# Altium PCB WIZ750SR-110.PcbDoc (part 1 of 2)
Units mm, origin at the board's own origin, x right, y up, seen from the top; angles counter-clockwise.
Board outline 63 x 45 mm, 4 copper layers (Top Layer, Internal Plane 1, Internal Plane 2, Bottom Layer); 95 components, 91 nets, 361 pads, 264 vias.
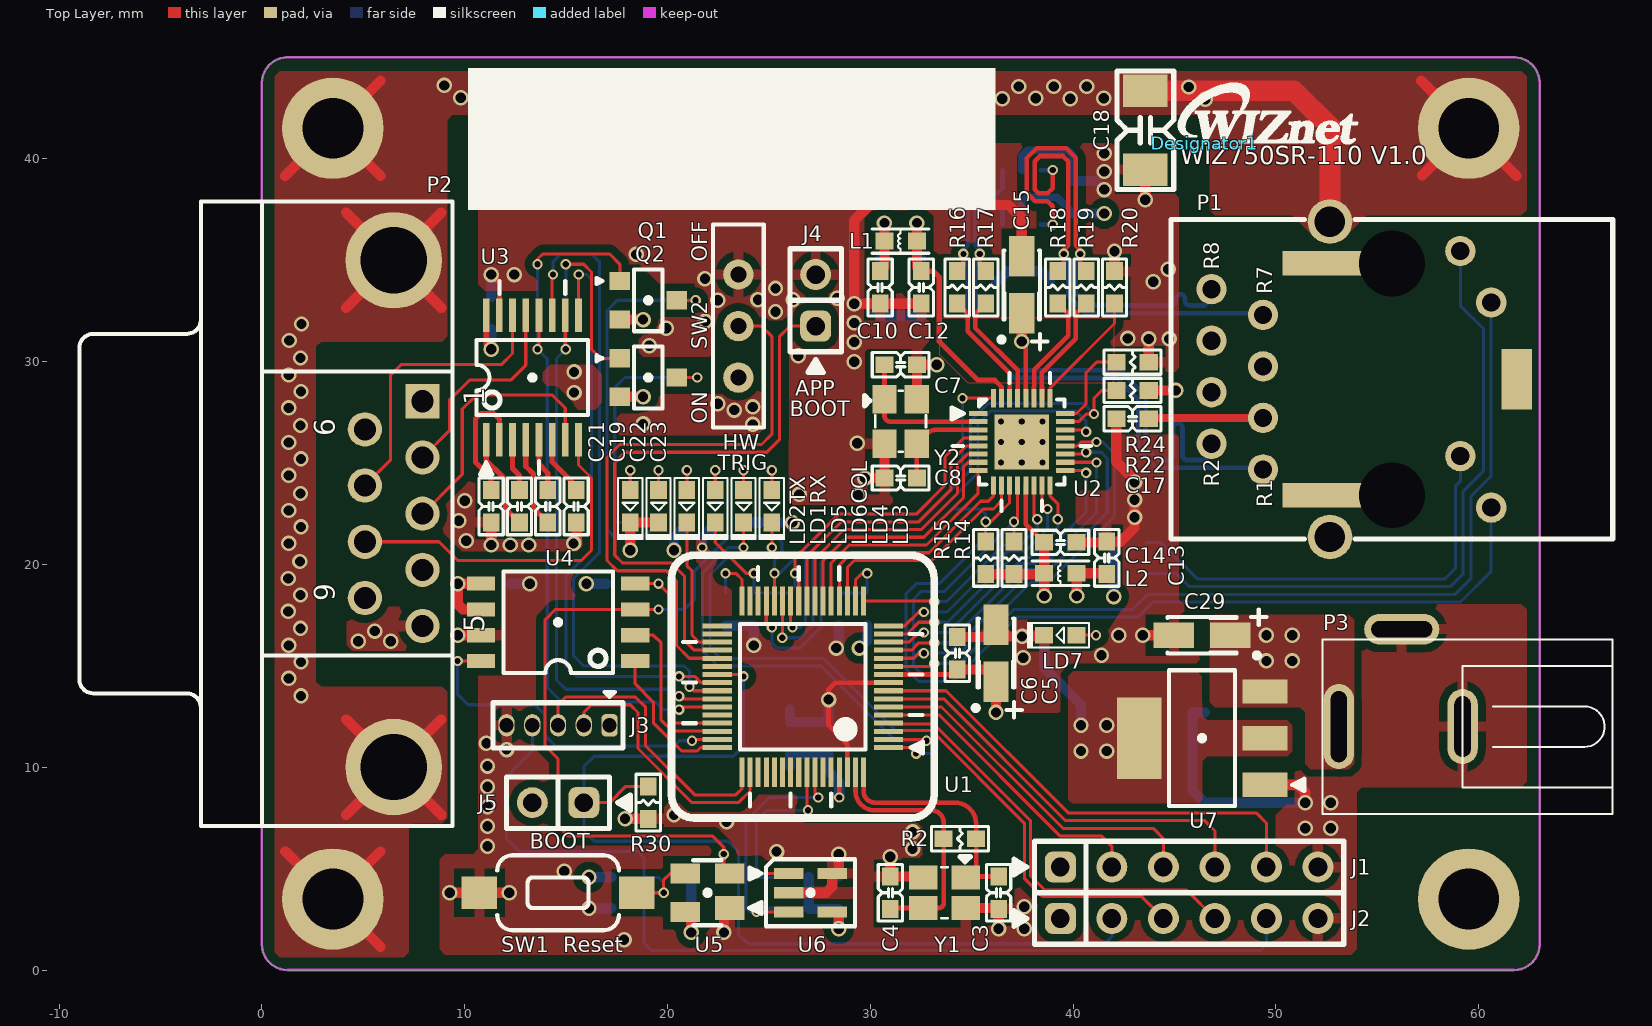
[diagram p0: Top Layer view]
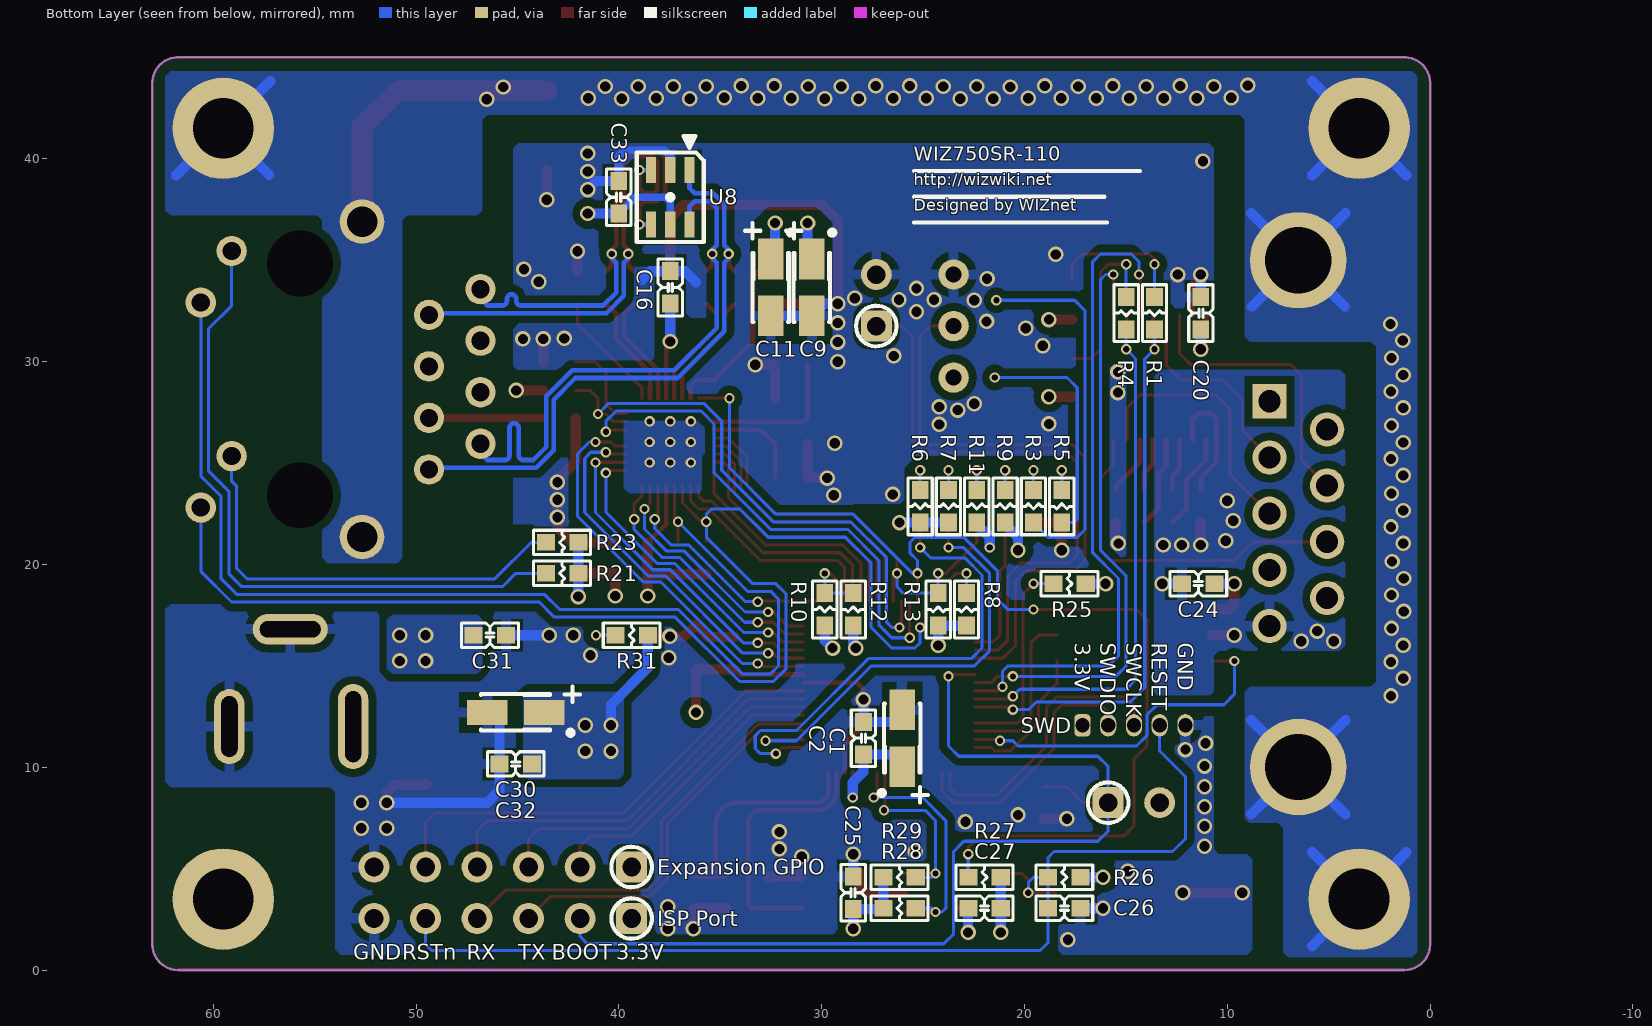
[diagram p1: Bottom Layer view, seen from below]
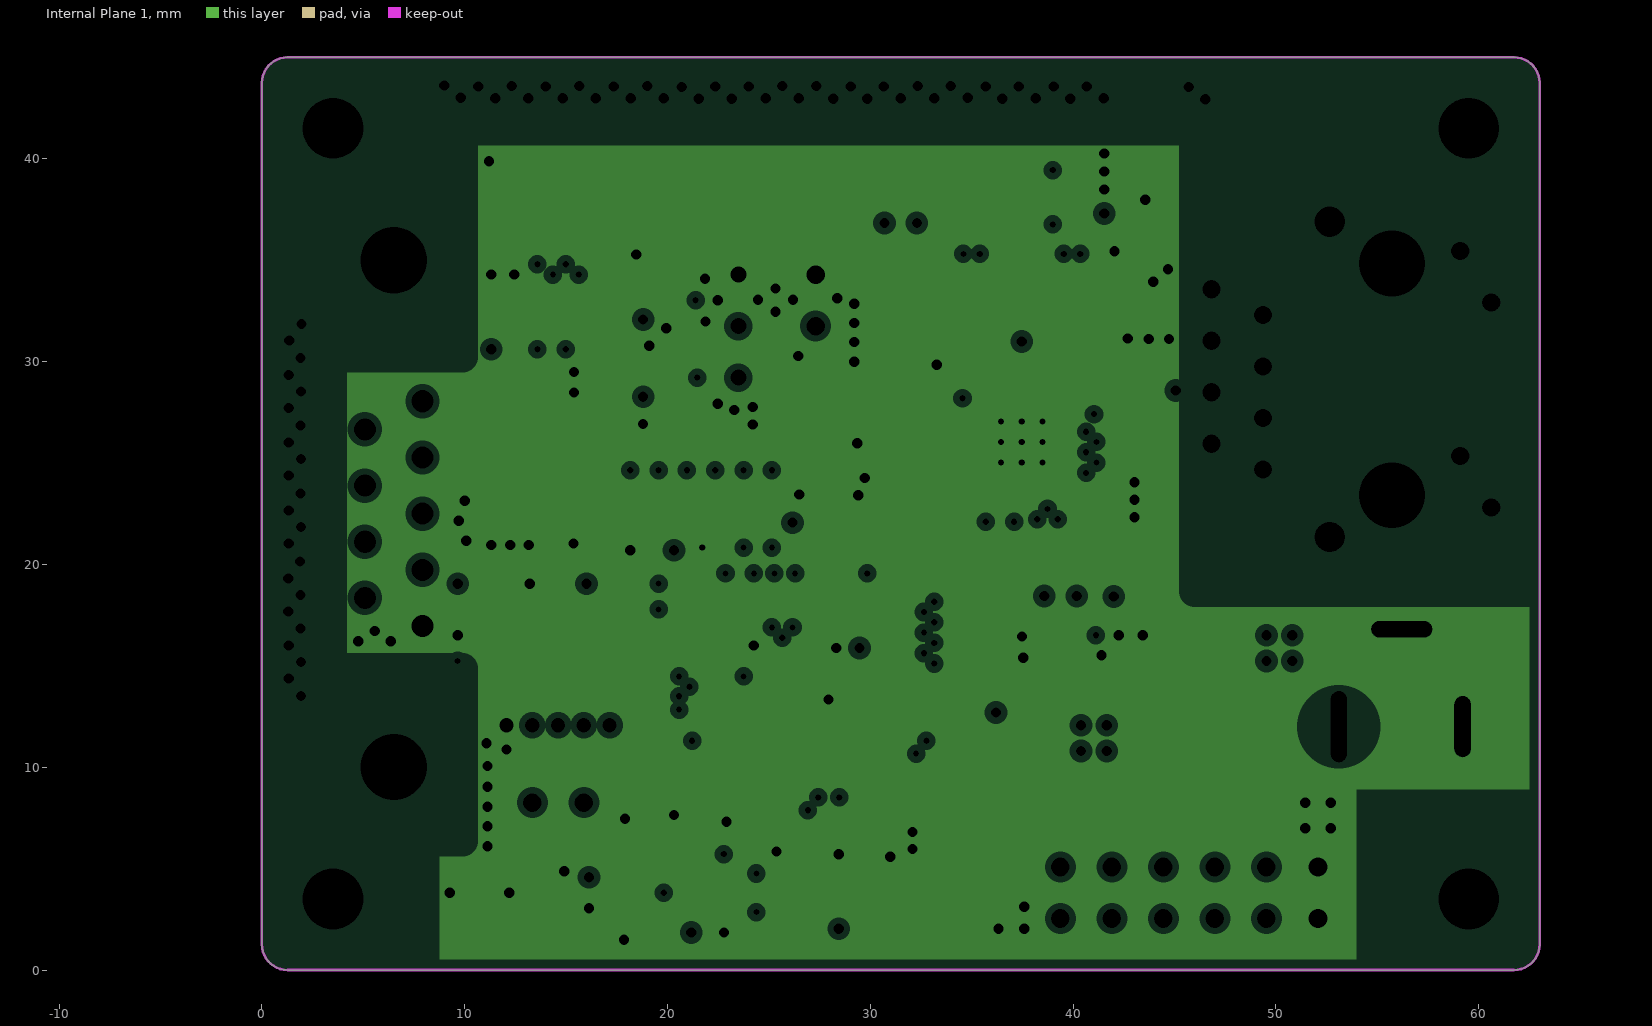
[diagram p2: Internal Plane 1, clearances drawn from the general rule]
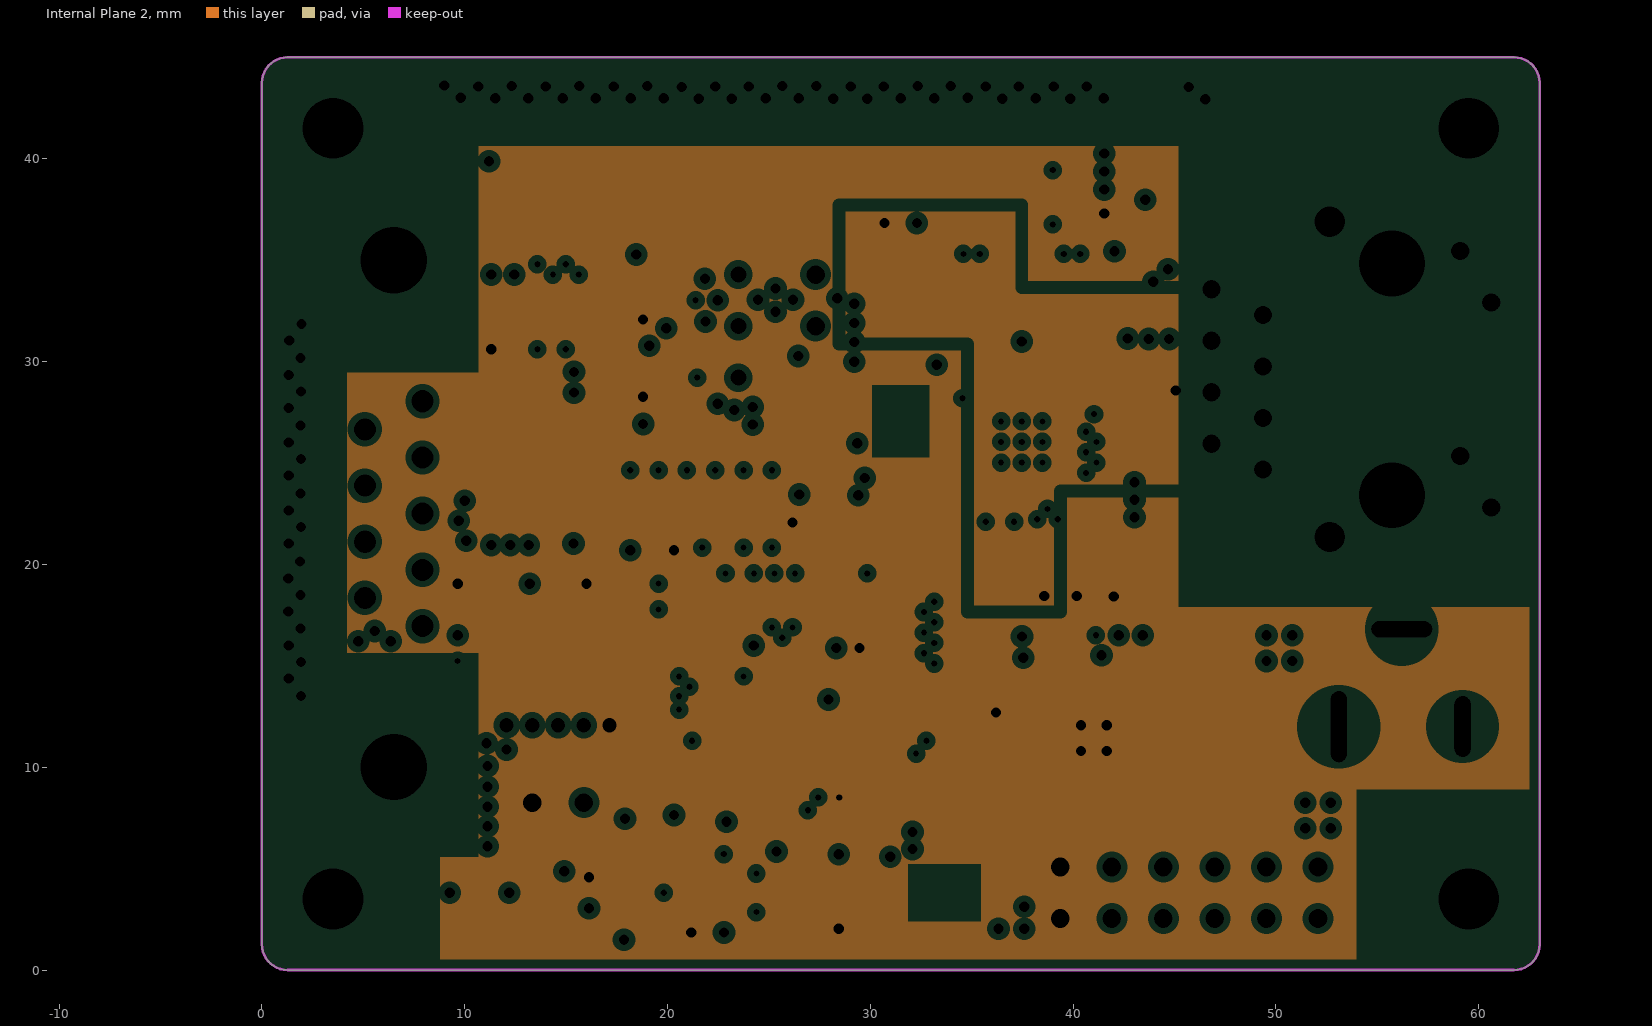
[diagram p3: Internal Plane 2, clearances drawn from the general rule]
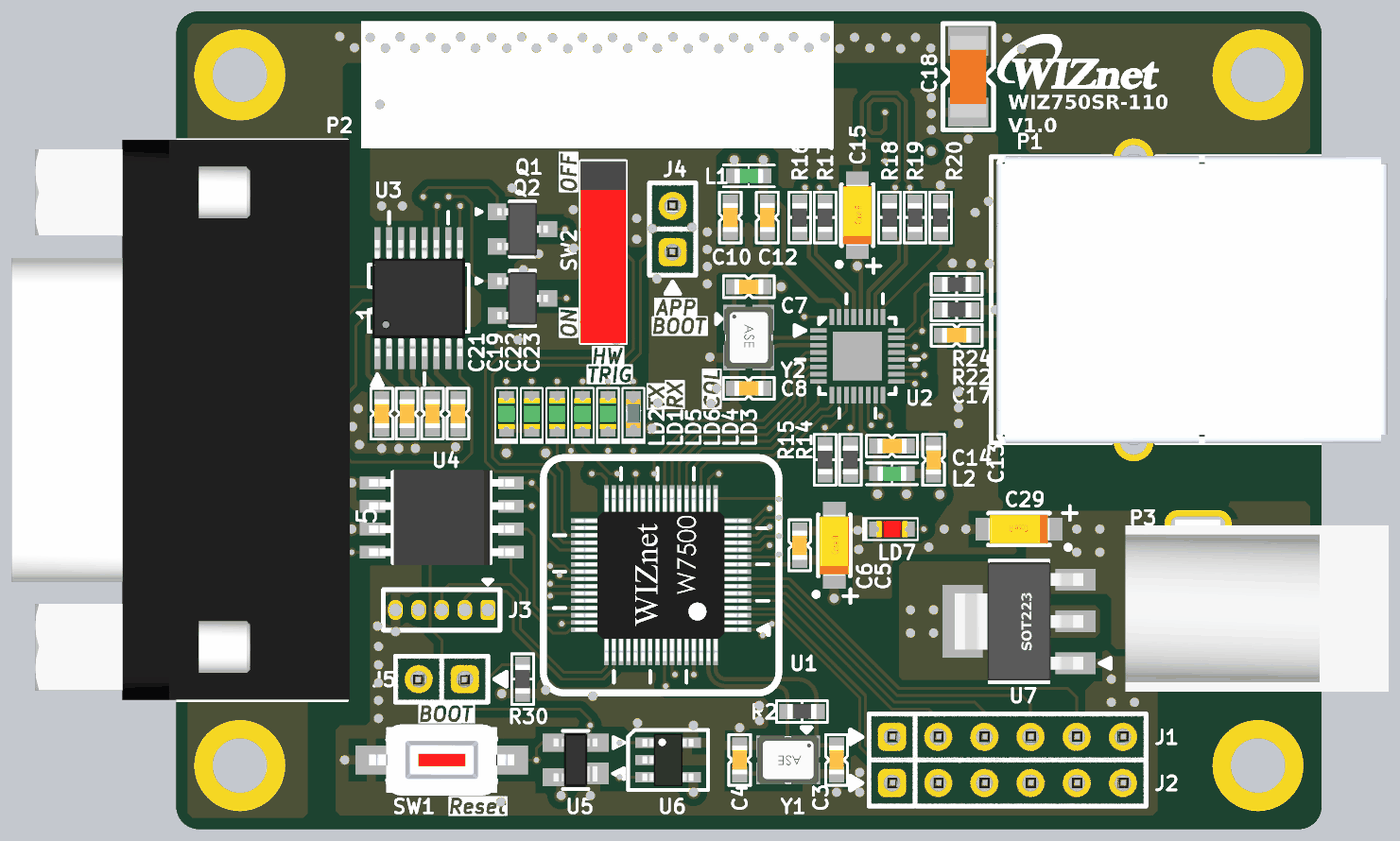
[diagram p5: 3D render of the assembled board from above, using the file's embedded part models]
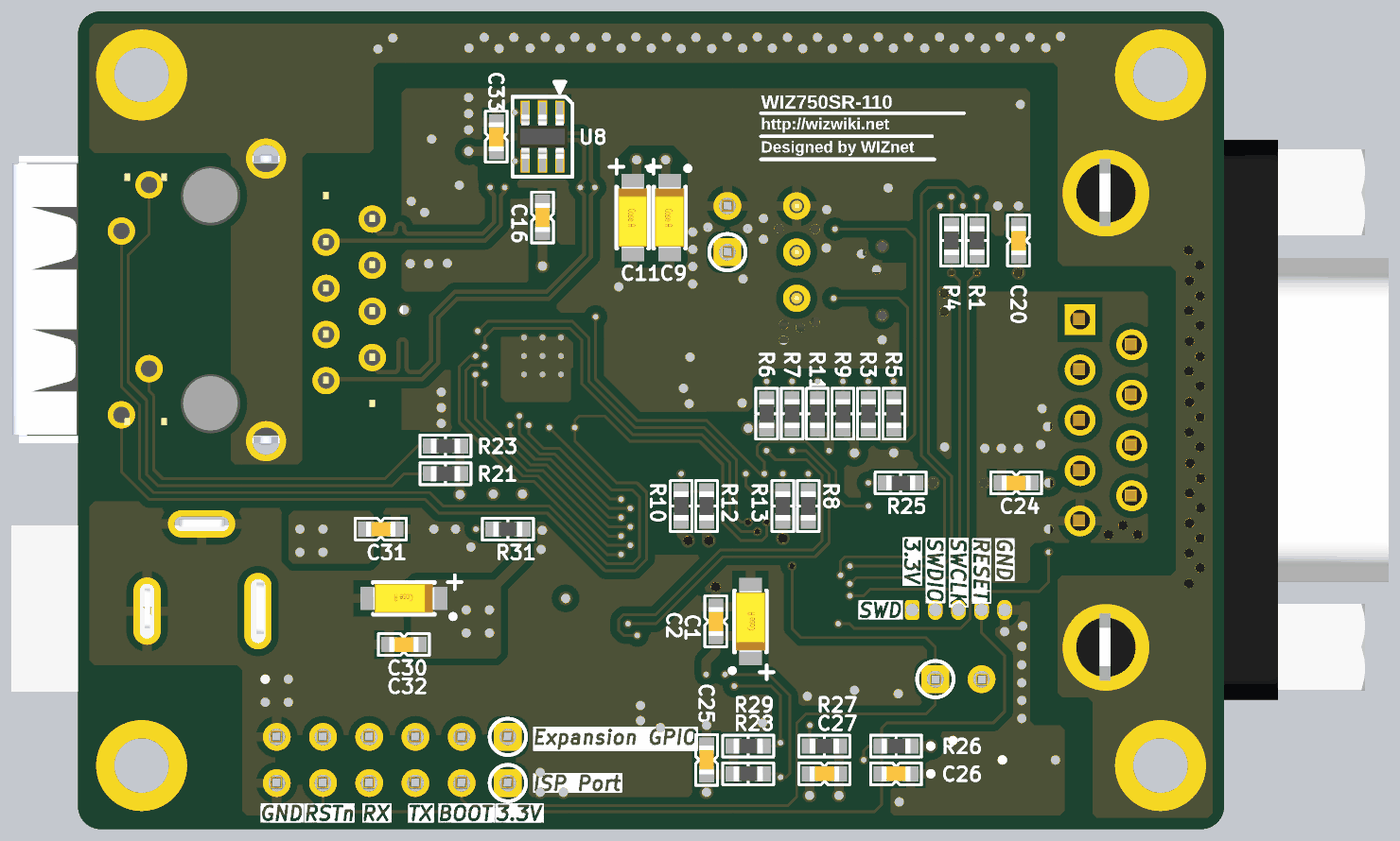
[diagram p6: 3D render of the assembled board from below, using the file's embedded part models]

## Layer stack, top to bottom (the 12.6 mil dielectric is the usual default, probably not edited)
Top Solder: solder mask 0.0102, Solder Resist, Dk 3.5
Top Layer: signal copper 0.0356
Dielectric1: core 0.32, FR-4, Dk 4.8
Internal Plane 1: plane copper 0.0356, net GND
Dielectric5: prepreg 0.32, FR-4, Dk 4.8
Internal Plane 2: plane copper 0.0356, net (Multiple Nets)
Dielectric6: core 0.32, FR-4, Dk 4.8
Bottom Layer: signal copper 0.0356
Bottom Solder: solder mask 0.0102, Solder Resist, Dk 3.5

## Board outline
0,1.27 0,43.73 cw(c1.27,43.73) 1.27,45 61.73,45 cw(c61.73,43.73) 63,43.73 63,1.27 cw(c61.73,1.27) 61.73,0 1.27,0 cw(c1.27,1.27)

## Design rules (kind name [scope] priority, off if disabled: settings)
Clearance [All] p1: gap=0.15 except(0.381: Arc-Poly Track-Poly SMDPad-Poly THPad-Poly Via-Poly Fill-Poly Poly-Poly Poly-Region)
DiffPairsRouting [All] p1: maxlimit=0.152 minlimit=0.152 mostfreqgap=0.152 toplayer_minwidth=0.152 toplayer_maxwidth=0.229 toplayer_prefwidth=0.229 bottomlayer_minwidth=0.152 bottomlayer_maxwidth=0.229 bottomlayer_prefwidth=0.229 maxuncoupledlength=15.24
HoleSize [All] p1: absolutevalues=TRUE maxlimit=4.064 minlimit=0.025 maxpercent=80.000 minpercent=20.000
PlaneClearance [All] p1: clearance=0.305
PlaneConnect [All] p1: planeconnectstyle=Direct reliefexpansion=0.508 reliefentries=4 reliefconductorwidth=0.254 reliefairgap=0.254
PolygonConnect PolygonConnect_2 [IsPad vs IsNamedPolygon('Top Layer-GND') Or  IsNamedPolygon('Bottom Layer-GND')] p1: connectstyle=Relief reliefconductorwidth=0.508 reliefentries=4 polygonreliefangle="90 Angle" airgapwidth=0.381
PolygonConnect PolygonConnect_1 [IsVia] p2: connectstyle=Direct reliefconductorwidth=0.254 reliefentries=4 polygonreliefangle="90 Angle" airgapwidth=0.254
PolygonConnect [All] p3: connectstyle=Direct reliefconductorwidth=0.254 reliefentries=4 polygonreliefangle="90 Angle" airgapwidth=0.254
RoutingVias [All] p1: holewidth=0.305 width=0.508 viastyle="Through Hole" minholewidth=0.305 minwidth=0.508 maxholewidth=0.508 maxwidth=0.762
SolderMaskExpansion [All] p1: expansion=0
Width [All] p1: maxlimit=2.54 minlimit=0.102 preferedwidth=0.152
26 further rules are at their usual default settings.

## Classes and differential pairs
component class 1.WIZ750JR_W7500: LD2
differential pair MDI_T: +MDI_T_P -MDI_T_N
differential pair MDI_R: +MDI_R_P -MDI_R_N
differential pair MDI0_T: +MDI0_T_P -MDI0_T_N
differential pair MDI0_R: +MDI0_R_P -MDI0_R_N
differential pair NewDifferentialPair1: +U_RXD2 -U_TXD2
differential pair NewDifferentialPair2: +U_RXD0 -U_TXD0
differential pair NewDifferentialPair3: +DB_RXD -DB_TXD

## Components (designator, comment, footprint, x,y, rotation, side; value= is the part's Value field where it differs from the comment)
C1 "10uF/16V" "CAP-A Size" 26.035,11.43 r90 bottom
C2 "1uF" CAP-0603 27.94,11.43 r270 bottom
C3 "30pF" CAP-0603 36.322,3.81 r90 top
C4 "30pF" CAP-0603 30.988,3.81 r270 top
C5 "10uF/16V" "CAP-A Size" 36.195,15.621 r90 top
C6 "1uF" CAP-0603 34.29,15.621 r270 top
C7 "27pF" CAP-0603 31.496,29.845 r180 top
C8 "27pF" CAP-0603 31.496,24.257 r0 top
C9 "10uF/16V" "CAP-A Size" 30.48,33.655 r270 bottom
C10 "0.1uF" CAP-0603 30.48,33.655 r90 top
C11 "10uF/16V" "CAP-A Size" 32.512,33.655 r270 bottom
C12 "0.1uF" CAP-0603 32.512,33.655 r90 top
C13 "0.1uF" CAP-0603 41.656,20.32 r270 top
C14 "0.1uF" CAP-0603 39.37,21.082 r0 top
C15 "10uF/16V" "CAP-A Size" 37.465,33.782 r90 top
C16 "0.1uF" CAP-0603 37.465,33.655 r270 bottom
C17 "0.1uF" CAP-0603 42.926,27.178 r0 top
C18 "1nF/2kV" CAP-1808 43.561,41.402 r90 top
C19 "0.1uF" CAP-0603 12.7,22.86 r90 top
C20 "0.1uF" CAP-0603 11.303,32.385 r270 bottom
C21 "0.1uF" CAP-0603 11.303,22.86 r90 top
C22 "0.1uF" CAP-0603 14.097,22.86 r90 top
C23 "0.1uF" CAP-0603 15.494,22.86 r90 top
C24 "0.1uF(NM)" CAP-0603 11.43,19.05 r0 bottom
C25 "0.1uF(NM)" CAP-0603 28.448,3.81 r270 bottom
C26 "0.1uF" CAP-0603 18.034,3.048 r0 bottom
C27 "0.1uF" CAP-0603 21.971,3.048 r180 bottom
C29 "10uF/16V" "CAP-A Size" 46.355,16.51 r180 top
C30 "10uF/16V" "CAP-A Size" 45.085,12.7 r0 bottom
C31 "0.1uF" CAP-0603 46.355,16.51 r0 bottom
C32 "0.1uF" CAP-0603 45.085,10.16 r180 bottom
C33 "0.1uF" CAP-0603 40.005,38.1 r90 bottom
Designator1 "Comment" LOGO-WIZNET(SMALL) 46.482,40.767 r0 top locked
J1 "2.54mm 1x6 Pin Header DIP" IDC-1X6 39.37,5.08 r0 top locked
J2 "2.54mm 1x6 Pin Header DIP(NM)" IDC-1X6 39.37,2.54 r0 top locked
J3 "1.27mm_1x5_Pin_header_DIP(NM)" IDC-1X5(1.27MM) 17.145,12.065 r180 top
J4 "2.54mm 1x2 Pin Header DIP" IDC-1X2 27.305,31.75 r90 top
J5 "2.54mm 1x2 Pin Header DIP" IDC-1X2 15.875,8.255 r180 top
L1 "HH-1M1608-121JT" IND-0603 31.496,35.941 r180 top
L2 "HH-1M1608-121JT" IND-0603 39.37,19.558 r180 top
LD1 "GREEN-0603" LED-0603-GREEN 19.558,22.86 r270 top
LD2 "GREEN-0603" LED-0603-GREEN 18.161,22.86 r270 top
LD3 "BLUE-0603" LED-0603-BLUE 25.146,22.86 r270 top
LD4 "GREEN-0603" LED-0603-GREEN 23.749,22.86 r270 top
LD5 "GREEN-0603" LED-0603-GREEN 20.955,22.86 r270 top
LD6 "GREEN-0603" LED-0603-GREEN 22.352,22.86 r270 top
LD7 "RED-0603" LED-0603-RED 39.37,16.51 r180 top
P1 "BS-RB10005" RJ45-RB10005 63,29.125 r90 top locked
P2 "D-SUB9-MALE" D-SUB9-MALE -3,22.5 r90 top locked
P3 "DC-JACK 2pi" "DC-JACK 2PI" 63,12 r90 top locked
Q1 "Q-MMBT4403" SOT-23-3L 19.05,33.02 r270 top
Q2 "Q-MMBT4403" SOT-23-3L 19.05,29.21 r270 top
R1 "1K" RES-0603 13.589,32.385 r270 bottom
R2 "1M" RES-0603 34.417,6.477 r180 top
R3 "330R" RES-0603 19.558,22.86 r270 bottom
R4 "1K" RES-0603 14.986,32.385 r270 bottom
R5 "330R" RES-0603 18.161,22.86 r90 bottom
R6 "1K" RES-0603 25.146,22.86 r270 bottom
R7 "330R" RES-0603 23.749,22.86 r270 bottom
R8 "4.7K" RES-0603 22.86,17.78 r90 bottom
R9 "330R" RES-0603 20.955,22.86 r270 bottom
R10 "4.7K/NC" RES-0603 29.845,17.78 r270 bottom
R11 "330R" RES-0603 22.352,22.86 r270 bottom
R12 "4.7K" RES-0603 28.448,17.78 r90 bottom
R13 "5.1K" RES-0603 24.257,17.78 r90 bottom
R14 "5.1K" RES-0603 37.084,20.32 r90 top
R15 "5.1K" RES-0603 35.687,20.32 r90 top
R16 "3.3R" RES-0603 34.29,33.655 r270 top
R17 "3.3R" RES-0603 35.687,33.655 r270 top
R18 "3.3R" RES-0603 39.243,33.655 r270 top
R19 "3.3R" RES-0603 40.64,33.655 r270 top
R20 "6.19K / 1%" RES-0603 42.037,33.655 r270 top
R21 "330R" RES-0603 42.799,19.558 r0 bottom
R22 "5.1K" RES-0603 42.926,28.575 r0 top
R23 "330R" RES-0603 42.799,21.082 r0 bottom
R24 "5.1K" RES-0603 42.926,29.972 r180 top
R25 "4.7K(NM)" RES-0603 17.78,19.05 r180 bottom
R26 "4.7K" RES-0603 18.034,4.572 r180 bottom
R27 "4.7K" RES-0603 21.971,4.572 r180 bottom
R28 "4.7K(NM)" RES-0603 26.162,3.048 r0 bottom
R29 "4.7K(NM)" RES-0603 26.162,4.572 r0 bottom
R30 "4.7K" RES-0603 19.05,8.255 r270 top
R31 "330R" RES-0603 39.37,16.51 r0 bottom
SW1 "ITS-1107(SMD)" IT-1107(SMD) 14.605,3.81 r0 top
SW2 "ITS-12H" ITS-12H 23.495,31.75 r270 top
U1 "W7500" W7500-LQFP64 26.67,13.97 r180 top locked
U2 "IP101GR/GRI" QFN32(0.4/4X4) 37.465,26.035 r0 top locked
U3 "SP3232EBEY" TSSOP16(0.65/6.4) 13.335,29.21 r90 top
U4 "AT45DB161E-SHF-T" SO-08-EIAJ 14.605,17.145 r180 top
U5 "MIC811SUY" SOT-143 21.971,3.81 r90 top
U6 "24AA16T-I/OT" SOT-23-5L 27.051,3.81 r0 top
U7 "IL1117C-33ET" SOT-223 46.355,11.43 r90 top locked
U8 "TPD4S009" SOT-23-6L 37.465,38.1 r270 bottom
Y1 "12MHz" OSC-TZ1067B 33.655,3.81 r180 top
Y2 "25MHz" OSC-82J0626 31.496,27.051 r270 top

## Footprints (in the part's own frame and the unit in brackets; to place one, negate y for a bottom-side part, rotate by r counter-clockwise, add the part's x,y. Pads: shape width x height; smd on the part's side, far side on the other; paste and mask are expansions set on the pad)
CAP-0603 [mm] "Ceramic CAP 0603(1608)"
  rect 0.89x0.82 smd: 1(-0.8,0) 2(0.8,0)
  silkscreen extent -1.4,-0.6 1.4,0.6, body extent -0.93,-0.41 0.93,0.41, height 0.81
CAP-1808 [mm] "Ceramic CAP 1808(4520)"
  rect 1.6x2.2 smd: 1(-1.95,0) 2(1.95,0)
  silkscreen extent -2.92,-1.4 2.92,1.4, body extent -2.25,-1.02 2.25,1.01, height 2
"CAP-A Size" [mm] "Tantal CAP A Size EIA/IECQ 3216"
  rect 2x1.25 smd: 1(-1.4,0) 2(1.4,0)
  silkscreen extent -3.17,-1.27 1.7,1.12, body extent -1.7,-0.8 1.7,0.8, height 1.75
D-SUB9-MALE [mm] "D-SUB9, MALE, Right Angle;"
  rect 1.69x1.69 hole 1.09: 1(5.54,-10.92)
  round 1.69 hole 1.09: 2(2.77,-10.92) 3(0,-10.92) 4(-2.77,-10.92) 5(-5.54,-10.92) 6(4.155,-8.08) 7(1.385,-8.08) 8(-1.385,-8.08) 9(-4.155,-8.08)
  round 4.76 hole 3.26: 10(-12.495,-9.5) 11(12.495,-9.5)
  silkscreen extent -15.4,-12.4 15.4,6, body extent -15.38,-12.55 15.43,6.05, height 12.57
"DC-JACK 2PI" [mm] "DC-JACK 2pi"
  oval 4.2x1.5 hole 0.8 slot 3.5 at 0 deg: 1(0,9.9)
  oval 1.5x3.7 hole 0.8 slot 3 at 90 deg: 2(4.8,6.8)
  oval 3.7x1.5 hole 0.8 slot 3 at 0 deg: 3(0,3.8)
  silkscreen extent -4.3,-3.6 4.3,10.7, body extent -4.42,-3.69 5.05,10.79, height 11.18
IDC-1X2 [mil]
  rrect50% 60x60 hole 36: 1(0,0)
  round 60 hole 36: 2(100,0)
  silkscreen extent -90,-50 150,50, body extent -49,-49 151,51, height 336
IDC-1X5(1.27MM) [mm]
  rrect50% 0.8x1.1 hole 0.7: 1(0,0)
  oval 0.8x1.1 hole 0.7: 2(1.27,0) 3(2.54,0) 4(3.81,0) 5(5.08,0)
  silkscreen extent -0.66,-1.65 5.74,1.11
IDC-1X6 [mil] "6-Way 2.54 mm Male Header"
  rrect50% 60x60 hole 36: 1(0,0)
  round 60 hole 36: 2(100,0) 3(200,0) 4(300,0) 5(400,0) 6(500,0)
  silkscreen extent -90,-50 550,50, body extent -49,-49 551,51, height 336
IND-0603 [mm] "Inductor 0603(1608)"
  rect 0.89x0.82 smd: 1(-0.8,0) 2(0.8,0)
  Top Layer pour cut-out: -0.254,0.508 -0.254,-0.508 0.254,-0.508 0.254,0.508
  silkscreen extent -1.4,-0.6 1.4,0.6, body extent -0.8,-0.4 0.8,0.4, height 0.95
IT-1107(SMD) [mm]
  rect 1.75x1.6 smd: 1(-3.875,0) 2(3.875,0)
  silkscreen extent -3,-1.85 3,1.85, body extent -4,-1.8 4,1.8, height 2.6
ITS-12H [mm] "Through Hole Slide Switch SPDT On-On 500mA Slide"
  round 1.5 hole 0.8: 1(0,0) 2(2.54,0) 3(-2.54,0)
  silkscreen extent -5,-1.25 5,1.25, body extent -5,-1.25 5,1.25, height 6.4
LED-0603-BLUE [mm] "LED-0603-GREEN"
  rect 0.89x0.82 smd: 1(-0.8,0) 2(0.8,0)
  silkscreen extent -1.41,-0.65 1.65,0.65, body extent -0.8,-0.4 0.8,0.4, height 0.6
LED-0603-GREEN [mm] "LED-0603-GREEN"
  rect 0.89x0.82 smd: 1(-0.8,0) 2(0.8,0)
  silkscreen extent -1.41,-0.65 1.65,0.65, body extent -0.85,-0.45 0.85,0.45, height 0.9
LED-0603-RED [mm] "LED-0603-RED"
  rect 0.89x0.82 smd: 1(-0.8,0) 2(0.8,0)
  silkscreen extent -1.41,-0.65 1.65,0.65, body extent -0.85,-0.45 0.85,0.45, height 0.9
LOGO-WIZNET(SMALL) [mm]
  silkscreen extent -1.27,0 7.52,2.93
OSC-82J0626 [mm]
  rect 1.4x1.2 smd: 1(-1.1,-0.8) 2(1.1,-0.8) 3(1.1,0.8) 4(-1.1,0.8)
  silkscreen extent -1.5,-1.78 1.5,1.25, body extent -1.7,-1.35 1.7,1.35, height 1.06
OSC-TZ1067B [mm]
  rect 1.4x1.2 smd: 1(-1.05,-0.75) 2(1.05,-0.75) 3(1.05,0.75) 4(-1.05,0.75)
  silkscreen extent -1.27,-1.78 0.15,1.25, body extent -1.7,-1.35 1.7,1.35, height 1.06
QFN32(0.4/4X4) [mm]
  rect 0.9x0.25 smd: 1(-2.15,1.4) 2(-2.15,1) 3(-2.15,0.6) 4(-2.15,0.2) 5(-2.15,-0.2) 6(-2.15,-0.6) 7(-2.15,-1) 8(-2.15,-1.4) 17(2.15,-1.4) 18(2.15,-1) 19(2.15,-0.6) 20(2.15,-0.2) 21(2.15,0.2) 22(2.15,0.6) 23(2.15,1) 24(2.15,1.4)
  rect 0.25x0.9 smd: 9(-1.4,-2.15) 10(-1,-2.15) 11(-0.6,-2.15) 12(-0.2,-2.15) 13(0.2,-2.15) 14(0.6,-2.15) 15(1,-2.15) 16(1.4,-2.15) 25(1.4,2.15) 26(1,2.15) 27(0.6,2.15) 28(0.2,2.15) 29(-0.2,2.15) 30(-0.6,2.15) 31(-1,2.15) 32(-1.4,2.15)
  rect 2.7x2.7 smd: 33(0,0)
  silkscreen extent -3.45,-3.4 3.4,3.4, body extent -2.1,-2.1 2.1,2.1, height 0.76
RES-0603 [mm] "RES-0603"
  rect 0.89x0.82 smd: 1(-0.8,0) 2(0.8,0)
  silkscreen extent -1.4,-0.6 1.4,0.6, body extent -0.82,-0.41 0.83,0.41, height 0.46
RJ45-RB10005 [mm]
  round 2.2 hole 1.5: 0(-7.775,10.34) 0(7.775,10.34)
  round 1.5 hole 0.9: L1(6.325,3.91) L2(3.785,2.39) L3(-3.785,3.91) L4(-6.325,2.39) R1(-4.445,13.64) R2(-3.175,16.18) R3(-1.905,13.64) R4(-0.635,16.18) R5(0.635,13.64) R6(1.905,16.18) R7(3.175,13.64) R8(4.445,16.18)
  round 3 hole 3.25 unplated paste+0 mask+0.102: ""(-5.715,7.29) ""(5.715,7.29)
  rect 1.2x4.7 smd: ""(-5.715,10.34) ""(5.715,10.34)
  rect 3x1.5 smd: ""(0,1.14)
  silkscreen extent -7.88,-3.6 7.88,18.18, body extent -7.97,-3.61 8.03,17.89, height 12.67
SO-08-EIAJ [mm]
  rect 1.4x0.7 smd: 1(-3.8,1.905) 2(-3.8,0.635) 3(-3.8,-0.635) 4(-3.8,-1.905) 5(3.8,-1.905) 6(3.8,-0.635) 7(3.8,0.635) 8(3.8,1.905)
  silkscreen extent -2.7,-2.5 2.7,2.5, body extent -4,-2.62 4,2.63, height 2.58
SOT-23-3L [mm]
  rect 0.9x1 smd: 1(-0.95,-1.4) 2(0.95,-1.4) 3(0,1.4)
  silkscreen extent -1.53,-2.55 1.53,0.7, body extent -1.45,-1.4 1.45,1.4, height 1.28
SOT-23-5L [mm]
  rect 1.45x0.55 smd: 1(-1.075,0.95) 2(-1.075,0) 3(-1.075,-0.95) 4(1.075,-0.95) 5(1.075,0.95)
  silkscreen extent -3.01,-1.65 2.2,1.65, body extent -1.4,-1.45 1.4,1.45, height 1.45
SOT-23-6L [mm]
  rect 1.27x0.508 smd paste-0.07: 1(-1.34,0.95) 2(-1.34,0) 3(-1.34,-0.95) 4(1.34,-0.95) 5(1.34,0) 6(1.34,0.95)
  silkscreen extent -3.02,-1.65 2.2,1.65, body extent -1.21,-1.4 1.21,1.4, height 1.09
SOT-143 [mm]
  rect 1.2x1.44 smd: 1(-0.75,-1.1)
  rect 1x1.44 smd: 2(0.95,-1.1) 3(0.95,1.1) 4(-0.95,1.1)
  silkscreen extent -1.6,-2.65 1.6,0.7, body extent -1.46,-1.21 1.46,1.21, height 1
SOT-223 [mm]
  rect 1.2x2.2 smd: 1(-2.3,-3.1) 2(0,-3.1) 3(2.3,-3.1)
  rect 4x2.2 smd: 4(0,3.1)
  silkscreen extent -3.35,-5.03 3.35,1.63, body extent -3.25,-3.53 3.25,3.52, height 1.82
TSSOP16(0.65/6.4) [mil]
  rect 65x13 smd: 1(-121.04,89.57) 2(-121.04,63.98) 3(-121.04,38.39) 4(-121.04,12.8) 5(-121.04,-12.8) 6(-121.04,-38.39) 7(-121.04,-63.98) 8(-121.04,-89.57) 9(121.04,-89.57) 10(121.04,-63.98) 11(121.04,-38.39) 12(121.04,-12.8) 13(121.04,12.8) 14(121.04,38.39) 15(121.04,63.98) 16(121.04,89.57)
  silkscreen extent -188,-108 187,108, body extent -126,-100 126,100, height 47
W7500-LQFP64 [mm] "WIZnet ARM Cortex-M0, LQFP64, Pitch 0.40mm"
  rect 1.45x0.25 smd: 1(-4.225,3) 2(-4.225,2.6) 3(-4.225,2.2) 4(-4.225,1.8) 5(-4.225,1.4) 6(-4.225,1) 7(-4.225,0.6) 8(-4.225,0.2) 9(-4.225,-0.2) 10(-4.225,-0.6) 11(-4.225,-1) 12(-4.225,-1.4) 13(-4.225,-1.8) 14(-4.225,-2.2) 15(-4.225,-2.6) 16(-4.225,-3) 33(4.225,-3) 34(4.225,-2.6) 35(4.225,-2.2) 36(4.225,-1.8) 37(4.225,-1.4) 38(4.225,-1) 39(4.225,-0.6) 40(4.225,-0.2) 41(4.225,0.2) 42(4.225,0.6) 43(4.225,1) 44(4.225,1.4) 45(4.225,1.8) 46(4.225,2.2) 47(4.225,2.6) 48(4.225,3)
  rect 0.25x1.45 smd: 17(-3,-4.225) 18(-2.6,-4.225) 19(-2.2,-4.225) 20(-1.8,-4.225) 21(-1.4,-4.225) 22(-1,-4.225) 23(-0.6,-4.225) 24(-0.2,-4.225) 25(0.2,-4.225) 26(0.6,-4.225) 27(1,-4.225) 28(1.4,-4.225) 29(1.8,-4.225) 30(2.2,-4.225) 31(2.6,-4.225) 32(3,-4.225) 49(3,4.225) 50(2.6,4.225) 51(2.2,4.225) 52(1.8,4.225) 53(1.4,4.225) 54(1,4.225) 55(0.6,4.225) 56(0.2,4.225) 57(-0.2,4.225) 58(-0.6,4.225) 59(-1,4.225) 60(-1.4,4.225) 61(-1.8,4.225) 62(-2.2,4.225) 63(-2.6,4.225) 64(-3,4.225)
  silkscreen extent -6.48,-6.48 6.48,6.48, body extent -4.73,-4.74 4.73,4.72, height 1

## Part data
C1 C5 C9 C11 C15 C29 C30: library part "CAP-A Size", "Tantla CAP A Size EIA/IECQ 3216"
C2 C3 C4 C6 C7 C8 C10 C12 C13 C14 C16 C17 C19 C20 C21 C22 C23 C24 C25 C26 C27: library part CAP-0402, "Ceramic CAP 0402(1005)"
C18: library part CAP-1808, "Ceramic CAP 1808(4520)"
C31 C32 C33: library part CAP-0603, "Ceramic CAP 0603(1608)"
J2: library part "Header 6", "Header, 6-Pin"
J3: library part 1.27mm_1x5_Pin_header_DIP, "1.27mm_1x5_Pin_header_DIP"
J4 J5: library part "Header 1x2", "pin header 2.54mm 1x2"
L1 L2: library part IND-0603, "Inductor 0603(1608)"
LD1 LD2 LD3 LD4 LD5 LD6 LD7: library part LED-0603, "LED-0603"
P1: library part RB1-125BAG1A, "10/100 BASE-TX MAGJACK"
P2: "D-SUB-9, MALE,  Right Angle"
Q1 Q2: "PNP General-Purpose Amplifier"
R1 R2 R3 R4 R5 R6 R7 R8 R9 R10 R12 R13 R16 R17 R18 R19 R20 R21 R22 R23 R24 R25 R26 R27 R28 R29 R30: library part RES-0402, "RES-0402"
R11 R31: library part RES-0603, "RES-0603"
R14 R15: library part RES-0603, "RES-0402"
SW1: "TACT SW, SMD"
SW2: "Slide Switch"
U1: "WIZnet ARM Cortex-M0"
U3: "True +3.0V to +5.5V RS-232 Transceivers TSSOP16"
U4: "16-Mbit DataFlash, 2.3V or 2.5V Minimum SPI Serial Flash Memory"
U5: "Microprocessor Reset Circuits"
U6: library part 24AAxxT-i-OT, "SOT-23"
U7: "1A, 3.3V"
U8: library part tpd4s009, "6-PIN SOT DBVor DCK Package"
Y1: library part OSC-TZ1067B-12MHz, "X-tal 12MHz,3.2x2.5 SMD, CL=20pF"
Y2: library part OSC-82J0626-25MHz, "X-tal 25MHz,3.2x2.5 SMD, CL=18pF"

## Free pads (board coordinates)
  round 5 hole 3: 0(3.5,3.5) 0(3.5,41.5) 0(59.5,3.5) 0(59.5,41.5)

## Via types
v1: diameter 0.762, hole 0.508, Top Layer to Bottom Layer, tented both sides, 186 vias
v2: diameter 0.508, hole 0.305, Top Layer to Bottom Layer, tented both sides, 78 vias

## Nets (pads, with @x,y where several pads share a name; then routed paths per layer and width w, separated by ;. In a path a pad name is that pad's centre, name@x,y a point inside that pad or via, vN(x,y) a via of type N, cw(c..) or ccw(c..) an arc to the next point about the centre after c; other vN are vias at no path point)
5V: C29.1 C31.2 P3.1 U7.3
  other v1: 49.53,15.24 50.8,15.24 49.53,16.51 50.8,16.51
APP_BOOT: J4.1 U1.36 | length 29.1
  Top Layer w0.152: U1.36@22.445,15.77 21.314,15.77 20.828,16.256 20.828,19.431 20.193,20.066 17.78,20.066 17.399,20.447 17.399,25.019 17.907,25.527 24.892,25.527 25.527,26.162 25.527,31.242 26.035,31.75 J4.1@27.305,31.75
BOOT: J2.2 J5.1 R30.1 U1.39 | length 51.5
  Top Layer w0.152: J5.1@15.875,8.255 17.145,8.255 17.945,9.055 R30.1@19.05,9.055 ; U1.39@22.445,14.57 23.657,14.57 v2(23.749,14.478)
  Bottom Layer w0.152: v2(23.749,14.478) 23.749,11.049 23.241,10.541 16.383,10.541 15.875,10.033 J5.1@15.875,8.255 15.875,6.858 16.383,6.35 22.987,6.35 23.495,5.842 23.495,1.778 23.978,1.295 41.554,1.295 41.91,1.651 J2.2@41.91,2.54
CH_GND: C18.2 P1.0 P2.10 P2.11 pad.0@3.5,3.5 pad.0@3.5,41.5 pad.0@59.5,41.5 | length 126.6
  Top Layer w0.508: 1.151,5.849 pad.0@3.5,3.5 ; 1.151,39.151 pad.0@3.5,41.5 ; 4.151,7.656 P2.10@6.5,10.005 ; 4.151,12.354 P2.10@6.5,10.005 ; 4.151,32.646 P2.11@6.5,34.995 ; 4.151,37.344 P2.11@6.5,34.995 ; 5.849,1.151 pad.0@3.5,3.5 ; 5.849,5.849 pad.0@3.5,3.5 ; 5.849,39.151 pad.0@3.5,41.5 ; 5.849,43.849 pad.0@3.5,41.5 ; 8.849,7.656 P2.10@6.5,10.005 ; 8.849,12.354 P2.10@6.5,10.005 ; 8.849,32.646 P2.11@6.5,34.995 ; 8.849,37.344 P2.11@6.5,34.995 ; 57.151,43.849 pad.0@59.5,41.5 pad.0@59.517,41.483 ; 57.214,39.18 pad.0@59.517,41.483 ; pad.0@59.563,41.529 pad.0@59.517,41.483 ; 61.849,39.151 pad.0@59.517,41.483
  Top Layer w1.016: C18.2@43.561,43.352 50.882,43.352 52.66,41.574 P1.0@52.66,36.9
  Bottom Layer w0.508: 1.185,5.815 pad.0@3.5,3.5 ; 1.185,39.185 pad.0@3.5,41.5 ; 4.185,7.69 P2.10@6.5,10.005 ; 4.185,12.32 P2.10@6.5,10.005 ; 4.185,37.31 P2.11@6.46,35.035 ; 4.219,32.714 P2.11@6.5,34.995 ; 5.815,1.185 pad.0@3.5,3.5 ; 5.815,5.815 pad.0@3.5,3.5 ; 5.815,39.185 pad.0@3.5,41.5 ; 5.815,43.815 pad.0@3.5,41.5 ; 8.781,32.714 P2.11@6.5,34.995 ; 8.815,7.69 P2.10@6.5,10.005 ; 8.815,12.32 P2.10@6.5,10.005 ; 8.815,37.31 P2.11@6.517,35.012 ; 57.185,43.815 pad.0@59.5,41.5 pad.0@59.517,41.483 ; 57.248,39.214 pad.0@59.517,41.483 ; pad.0@59.563,41.529 pad.0@59.517,41.483 ; 61.815,39.185 pad.0@59.517,41.483 ; P2.11@6.46,35.035 6.477,35.052 P2.11@6.517,35.012 ; P2.11@6.46,35.035 P2.11@6.5,34.995 ; P2.11@6.5,34.995 P2.11@6.517,35.012
  other v1: 1.93,13.513 1.321,14.376 1.93,15.189 1.321,16.002 1.905,16.84 1.295,17.678 1.905,18.491 1.295,19.304 1.88,20.142 1.321,21.031 1.93,21.844 1.321,22.657 1.905,23.495 1.321,24.384 1.93,25.197 1.321,26.01 1.905,26.848 1.321,27.711 1.93,28.524 1.321,29.337 1.905,30.175 1.346,31.039 1.956,31.852 46.507,42.926 21.539,42.951 23.165,42.951 28.169,42.951 29.845,42.951 36.5,42.951 39.853,42.951 11.506,42.977 13.132,42.977 14.834,42.977 16.459,42.977 18.186,42.977 19.812,42.977 24.841,42.977 26.467,42.977 31.496,42.977 33.147,42.977 38.151,42.977 41.504,42.977 9.804,43.002 34.798,43.002 20.701,43.536 45.695,43.536 10.668,43.561 13.995,43.561 17.348,43.561 22.352,43.561 24.003,43.561 29.032,43.561 30.658,43.561 35.687,43.561 37.313,43.561 39.04,43.561 40.665,43.561 12.319,43.586 15.646,43.586 18.999,43.586 25.654,43.586 27.33,43.586 32.334,43.586 33.96,43.586 8.992,43.612
DB_CTS: P2.8 U3.8 | length 17.5
  Top Layer w0.152: P2.8@5.08,21.115 8.73,21.115 9.652,20.193 15.748,20.193 16.256,20.701 16.256,24.257 15.61,24.903 U3.8@15.61,26.136
DB_RTS: P2.7 U3.14 | length 14.3
  Top Layer w0.152: P2.7@5.08,23.885 6.35,25.155 6.35,29.337 6.858,29.845 11.811,29.845 12.36,30.394 U3.14@12.36,32.284
DB_RXD: P2.2 U3.13 | length 10.3
  Top Layer w0.152: P2.2@7.92,25.27 9.246,26.596 9.246,28.092 10.236,29.083 12.268,29.083 13.01,29.825 U3.13@13.01,32.284
DB_TXD: P2.3 U3.7 | length 13.2
  Top Layer w0.152: P2.3@7.92,22.5 7.945,22.5 9.614,24.168 9.881,24.436 9.881,27.661 10.566,28.346 14.326,28.346 14.96,27.712 U3.7@14.96,26.136
DUP: R10.1 R12.2 U1.18 | length 4.1
  Top Layer w0.152: U1.18@29.27,18.195 29.27,19.237 29.591,19.558 v2(29.845,19.558)
  Bottom Layer w0.152: R12.2@28.448,18.58 R10.1@29.845,18.58 v2(29.845,19.558)
EX_RESETN: C26.2 J2.5 J3.4 R26.1 SW1.2 U5.3 | length 54.5
  Top Layer w0.152: SW1.2@18.48,3.81 v2(19.812,3.81) 19.812,4.445 20.127,4.76 U5.3@20.871,4.76
  Bottom Layer w0.152: J3.4@13.335,12.065 13.335,10.795 12.065,9.525 12.065,6.477 12.7,5.842 18.542,5.842 18.834,5.55 R26.1@18.834,4.572 ; v2(19.812,3.81) 19.812,4.318 19.558,4.572 R26.1@18.834,4.572 ; J2.5@49.53,2.54 49.53,1.27 49.225,0.965 19.228,0.965 18.834,1.359 C26.2@18.834,3.048 R26.1@18.834,4.572
EXPANSION_GPIO_A: J1.5 U1.8 | length 23.5
  Top Layer w0.152: U1.8@30.895,13.77 33.728,13.77 39.751,7.747 49.022,7.747 49.53,7.239 J1.5@49.53,5.08
EXPANSION_GPIO_B: J1.4 U1.7 | length 20.6
  Top Layer w0.152: U1.7@30.895,13.37 33.62,13.37 39.624,7.366 46.482,7.366 46.99,6.858 J1.4@46.99,5.08
EXPANSION_GPIO_C: J1.3 U1.6 | length 17.6
  Top Layer w0.152: U1.6@30.895,12.97 33.512,12.97 39.497,6.985 43.942,6.985 44.45,6.477 J1.3@44.45,5.08
EXPANSION_GPIO_D: J1.2 U1.5 | length 14.7
  Top Layer w0.152: U1.5@30.895,12.57 33.404,12.57 39.37,6.604 41.402,6.604 41.91,6.096 J1.2@41.91,5.08
GND: C1.2 C2.1 C3.1 C4.1 C5.2 C6.1 C7.1 C8.1 C9.2 C10.1 C11.2 C12.1 C13.1 C14.2 C15.2 C16.1 C17.1 C18.1 C20.1 C21.1 C23.1 C24.2 C25.1 C26.1 C27.1 C29.2 C30.2 C31.1 C32.1 C33.2 J1.6 J2.6 J3.5 J4.2 LD1.2 LD2.2 LD7.2 P2.5 P3.2 P3.3 R8.1 R11.2 R12.1 R13.1 R20.1 R24.1 R30.2 SW1.1 SW2.3 U1.9 U1.62 U2.33 U3.15 U4.7 U5.1 U6.2 U6.5 U7.1 U8.2 Y1.2 Y1.4 Y2.2 Y2.4 | length 114.4
  Top Layer w0.229: U1.62@28.87,9.745 28.87,11.135 27.94,12.065 v1(27.94,13.335) 27.94,13.843 28.267,14.17 U1.9@30.895,14.17
  Top Layer w0.254: v1(11.303,34.29) 11.71,33.883 U3.15@11.71,32.284
  Top Layer w0.508: v1(9.271,3.81) SW1.1@10.73,3.81 v1(12.192,3.81) ; v1(9.652,16.51) U4.7@10.805,16.51 ; v1(11.303,20.955) C21.1@11.303,22.06 ; v1(15.367,21.031) 15.519,21.184 15.519,22.035 C23.1@15.494,22.06 ; v1(17.907,7.455) R30.2@19.05,7.455 ; v1(18.161,20.701) LD2.2@18.161,22.06 LD1.2@19.558,22.06 ; v1(22.784,1.854) 22.784,2.646 22.835,2.696 22.771,2.76 U5.1@23.071,3.06 ; U6.2@25.976,3.81 27.813,3.81 28.126,4.123 U6.5@28.126,4.76 28.448,4.76 v1(28.448,5.715) ; v1(29.718,24.257) C8.1@30.696,24.257 Y2.2@30.696,25.951 ; v1(30.988,5.588) C4.1@30.988,4.61 32.555,4.61 Y1.2@32.605,4.56 ; Y2.4@32.296,28.151 C7.1@32.296,29.845 v1(33.274,29.845) ; C12.1@32.512,32.855 C10.1@30.48,32.855 v1(29.21,32.855) 29.21,36.957 29.972,37.719 36.83,37.719 37.465,37.084 C15.2@37.465,35.182 ; C6.1@34.29,16.421 35.595,16.421 C5.2@36.195,17.021 36.768,16.448 v1(37.481,16.448) 38.508,16.448 LD7.2@38.57,16.51 ; Y1.4@34.705,3.06 36.272,3.06 C3.1@36.322,3.01 v1(36.322,2.032) ; C14.2@40.17,21.082 41.618,21.082 C13.1@41.656,21.12 42.329,21.12 43.028,21.819 v1(43.028,23.19) ; R20.1@42.037,34.455 v1(42.037,35.433) ; C17.1@42.126,27.178 42.126,25.057 43.028,24.155 v1(43.028,24.054) ; v1(43.434,16.51) C29.2@44.955,16.51 ; v1(43.561,37.973) C18.1@43.561,39.452 ; R24.1@43.726,29.972 v1(43.726,31.115) ; U7.1@49.455,9.13 51.068,9.13 51.435,8.763 v1(51.435,8.255)
  Bottom Layer w0.381: U8.2@37.465,39.44 37.465,40.132 37.748,40.415 39.722,40.415 40.005,40.132 C33.2@40.005,38.9
  Bottom Layer w0.508: C20.1@11.303,33.185 v1(11.303,34.29) ; C24.2@12.23,19.05 v1(13.208,19.05) ; v1(16.129,3.048) C26.1@17.234,3.048 ; v2(21.717,20.828) 21.717,21.344 22.352,21.979 R11.2@22.352,22.06 ; C27.1@22.771,3.048 22.835,2.984 22.784,2.934 v1(22.784,1.854) ; R8.1@22.86,16.98 R13.1@24.257,16.98 v1(24.257,16.002) ; C1.2@26.035,12.83 26.035,12.23 C2.1@27.94,12.23 v1(27.94,13.335) ; v1(28.321,15.875) 28.448,16.002 R12.1@28.448,16.98 ; C25.1@28.448,4.61 v1(28.448,5.715) ; v1(29.21,32.855) 29.88,32.855 C9.2@30.48,32.255 C11.2@32.512,32.255 ; 36.195,33.909 36.741,34.455 C16.1@37.465,34.455 38.443,34.455 38.862,34.036 ; C33.2@40.005,38.9 41.11,38.9 v1(41.529,38.481) ; v1(43.434,16.51) C31.1@45.555,16.51 ; C30.2@46.485,12.7 45.885,12.7 C32.1@45.885,10.16 45.885,8.852 46.482,8.255 v1(51.435,8.255)
  other v1: 17.856,1.499 37.592,2.032 37.592,3.124 14.91,4.877 25.375,5.842 32.08,5.969 11.125,6.096 32.08,6.807 51.435,6.985 52.705,6.985 11.125,7.087 22.911,7.315 20.32,7.645 11.125,8.052 52.705,8.255 11.125,9.042 11.125,10.058 12.065,10.871 11.074,11.176 37.541,15.392 41.397,15.524 4.75,16.205 6.35,16.205 42.24,16.51 5.563,16.713 12.243,20.955 13.157,20.955 10.084,21.158 9.703,22.149 43.028,22.327 10.008,23.139 29.406,23.407 26.493,23.449 29.355,25.972 24.206,26.899 18.796,26.924 23.292,27.61 24.206,27.762 22.479,27.915 15.391,28.469 15.392,29.489 29.21,29.997 26.441,30.277 19.101,30.785 29.21,30.963 44.729,31.115 42.697,31.14 19.939,31.648 29.21,31.902 21.869,31.979 25.324,32.461 22.479,33.02 24.46,33.045 26.187,33.045 28.372,33.122 25.324,33.604 43.942,33.934 21.844,34.087 12.446,34.29 44.679,34.544 18.466,35.281 41.529,39.37 11.201,39.878 41.529,40.259
  other v2: 36.449,25.019 37.465,25.019 38.481,25.019 36.449,26.035 37.465,26.035 38.481,26.035 36.449,27.051 37.465,27.051 38.481,27.051
HW_TRIG: SW2.1 U1.37 | length 29.7
  Top Layer w0.152: U1.37@22.445,15.37 21.079,15.37 20.447,16.002 20.447,19.177 19.939,19.685 17.526,19.685 17.018,20.193 17.018,25.273 17.653,25.908 24.638,25.908 25.146,26.416 25.146,31.242 24.638,31.75 SW2.1@23.495,31.75
IP_3.3A: C11.1 C12.2 L1.1 U2.31 | length 13.1
  Top Layer w0.229: 36.135,29.083 36.465,28.753 U2.31@36.465,28.185
  Top Layer w0.254: C12.2@32.512,34.455 33.109,34.455 33.401,34.163 33.401,30.988 35.306,29.083 36.135,29.083
  Top Layer w0.508: v1(32.296,36.83) L1.1@32.296,35.941 32.296,34.671 C12.2@32.512,34.455
  Bottom Layer w0.508: v1(32.296,36.83) 32.296,35.271 C11.1@32.512,35.055
IP_3.3V: C9.1 C10.2 C14.1 L1.2 L2.2 R14.1 R15.1 R22.2 U2.13 | length 14.4
  Top Layer w0.229: U2.13@37.665,23.885 37.665,21.987 C14.1@38.57,21.082
  Top Layer w0.508: C10.2@30.48,34.455 30.696,34.671 L1.2@30.696,35.941 v1(30.696,36.83) ; R15.1@35.687,19.52 R14.1@37.084,19.52 38.532,19.52 L2.2@38.57,19.558 ; v1(38.57,18.44) L2.2@38.57,19.558 ; C14.1@38.57,21.082 L2.2@38.57,19.558 ; R22.2@43.726,28.575 v1(45.06,28.575)
  Bottom Layer w0.508: C9.1@30.48,35.055 30.696,35.271 v1(30.696,36.83)
MDI0_R_N: R19.2 U2.26 | length 5.6
  Top Layer w0.229: U2.26@38.465,28.185 38.465,28.749 38.456,28.759 38.456,29.439 40.132,31.115 40.132,32.347 R19.2@40.64,32.855
MDI0_R_P: R18.2 U2.27 | length 5.6
  Top Layer w0.229: U2.27@38.065,28.185 38.065,28.749 38.075,28.759 38.075,29.596 39.751,31.273 39.751,32.347 R18.2@39.243,32.855
MDI0_T_N: R17.2 U2.29 | length 5.7
  Top Layer w0.229: R17.2@35.687,32.855 35.179,32.347 35.179,31.654 37.265,29.568 U2.29@37.265,28.185
MDI0_T_P: R16.2 U2.30 | length 5.7
  Top Layer w0.229: R16.2@34.29,32.855 34.798,32.347 34.798,31.496 36.865,29.429 U2.30@36.865,28.185
MDI_R_N: P1.R8 R19.1 U8.4 | length 23.6
  Top Layer w0.229: v2(38.989,36.76) 38.989,37.655 38.735,37.91 38.133,37.91 37.719,38.323 37.719,40.036 38.196,40.513 39.655,40.513 40.132,40.036 40.132,35.732 40.345,35.519 v2(40.345,35.309) 40.345,34.75 R19.1@40.64,34.455
  Bottom Layer w0.229: U8.4@38.415,36.76 v2(38.989,36.76) ; v2(40.345,35.309) 40.345,35.093 40.132,34.88 40.132,33.401 40.767,32.766 44.831,32.766 ccw(c44.831,32.995) 45.06,32.995 45.06,33.087 cw(c45.288,33.087) 45.288,33.316 cw(c45.288,33.087) 45.517,33.087 45.517,32.995 ccw(c45.745,32.995) 45.745,32.766 45.974,32.766 46.482,32.766 46.82,33.104 P1.R8@46.82,33.57
MDI_R_P: P1.R7 R18.1 U8.3 | length 23.6
  Top Layer w0.229: v2(38.989,39.44) 38.989,38.544 38.735,38.291 38.291,38.291 38.1,38.481 38.1,39.878 38.354,40.132 39.497,40.132 39.751,39.878 39.751,35.73 39.539,35.518 v2(39.539,35.309) 39.539,34.751 R18.1@39.243,34.455
  Bottom Layer w0.229: U8.3@38.415,39.44 v2(38.989,39.44) ; v2(39.539,35.309) 39.539,35.094 39.751,34.882 39.751,33.243 40.609,32.385 49.275,32.385 P1.R7@49.36,32.3
MDI_T_N: P1.R2 R17.1 U8.6 | length 29.2
  Top Layer w0.229: v2(35.391,35.308) 35.391,34.753 35.408,34.77 35.433,34.745 35.433,34.709 R17.1@35.687,34.455
  Bottom Layer w0.229: U8.6@36.515,36.76 36.515,37.653 36.258,37.91 35.496,37.91 35.179,37.592 35.179,35.728 35.391,35.516 v2(35.391,35.308) 35.391,35.096 35.179,34.884 35.179,31.654 37.263,29.57 42.299,29.57 43.586,28.283 43.586,25.786 44.227,25.146 44.704,25.146 ccw(c44.704,25.375) 44.933,25.375 44.933,26.73 cw(c45.161,26.73) 45.161,26.958 cw(c45.161,26.73) 45.39,26.73 45.39,25.375 ccw(c45.618,25.375) 45.618,25.146 45.847,25.146 46.482,25.146 46.82,25.484 P1.R2@46.82,25.95
MDI_T_P: P1.R1 R16.1 U8.1 | length 29.3
  Top Layer w0.229: R16.1@34.29,34.455 34.544,34.709 34.544,34.795 34.586,34.753 v2(34.586,35.31)
  Bottom Layer w0.229: U8.1@36.515,39.44 36.515,38.547 36.258,38.291 35.339,38.291 34.798,37.75 34.798,35.728 34.586,35.516 v2(34.586,35.31) 34.586,35.096 34.798,34.884 34.798,31.496 37.105,29.189 42.141,29.189 43.205,28.125 43.205,25.629 44.069,24.765 49.275,24.765 P1.R1@49.36,24.68
NetC15_1: C15.1 C16.2 U2.28 | length 6.1
  Top Layer w0.229: v1(37.465,30.988) 37.665,30.788 U2.28@37.665,28.185
  Top Layer w0.508: v1(37.465,30.988) C15.1@37.465,32.382
  Bottom Layer w0.508: v1(37.465,30.988) C16.2@37.465,32.855
NetC17_2: C17.2 P1.R3 | length 5.7
  Top Layer w0.381: C17.2@43.726,27.178 43.768,27.22 P1.R3@49.36,27.22
NetC19_1: C19.1 U3.1 | length 4.8
  Top Layer w0.254: U3.1@11.06,26.136 11.06,25.135 11.813,24.382 11.828,24.382 12.013,24.197 12.013,22.747 C19.1@12.7,22.06
NetC19_2: C19.2 U3.3 | length 2.6
  Top Layer w0.254: U3.3@12.36,26.136 12.36,24.724 12.7,24.384 C19.2@12.7,23.66
NetC21_2: C21.2 U3.2 | length 6.2
  Top Layer w0.254: C21.2@11.303,23.66 11.303,24.257 10.541,25.019 10.541,27.178 10.795,27.432 11.43,27.432 11.71,27.152 U3.2@11.71,26.136
NetC22_1: C22.1 U3.4 | length 4.5
  Top Layer w0.254: U3.4@13.01,26.136 13.01,24.836 13.387,24.459 13.387,22.77 C22.1@14.097,22.06
NetC22_2: C22.2 U3.5 | length 2.7
  Top Layer w0.254: U3.5@13.66,26.136 13.66,24.948 14.097,24.511 C22.2@14.097,23.66
NetC23_2: C23.2 U3.6 | length 3
  Top Layer w0.254: U3.6@14.31,26.136 14.31,25.06 15.494,23.876 C23.2@15.494,23.66
NetLD1_1: LD1.1 R3.1 | length 2
  Top Layer w0.152: LD1.1@19.558,23.66 v2(19.558,24.638)
  Bottom Layer w0.152: R3.1@19.558,23.66 v2(19.558,24.638)
NetLD2_1: LD2.1 R5.2 | length 2
  Top Layer w0.152: LD2.1@18.161,23.66 v2(18.161,24.638)
  Bottom Layer w0.152: R5.2@18.161,23.66 v2(18.161,24.638)
NetLD3_1: LD3.1 R6.1 | length 2
  Top Layer w0.152: LD3.1@25.146,23.66 v2(25.146,24.638)
  Bottom Layer w0.152: R6.1@25.146,23.66 v2(25.146,24.638)
NetLD4_1: LD4.1 R7.1 | length 2
  Top Layer w0.152: LD4.1@23.749,23.66 v2(23.749,24.638)
  Bottom Layer w0.152: R7.1@23.749,23.66 v2(23.749,24.638)
NetLD5_1: LD5.1 R9.1 | length 2
  Top Layer w0.152: LD5.1@20.955,23.66 v2(20.955,24.638)
  Bottom Layer w0.152: R9.1@20.955,23.66 v2(20.955,24.638)
NetLD6_1: LD6.1 R11.1 | length 2
  Top Layer w0.152: LD6.1@22.352,23.66 v2(22.352,24.638)
  Bottom Layer w0.152: R11.1@22.352,23.66 v2(22.352,24.638)
NetLD7_1: LD7.1 R31.2 | length 1.9
  Top Layer w0.152: LD7.1@40.17,16.51 v2(41.123,16.51)
  Bottom Layer w0.152: R31.2@40.17,16.51 v2(41.123,16.51)
NetP1_L1: P1.L1 R21.2 | length 33
  Bottom Layer w0.152: R21.2@43.599,19.558 45.085,19.558 45.739,18.904 58.589,18.904 59.224,19.539 59.224,23.603 60.24,24.619 60.24,31.604 59.09,32.754 P1.L1@59.09,35.45
NetP1_L3: P1.L3 R23.2 | length 21.8
  Bottom Layer w0.152: R23.2@43.599,21.082 44.323,21.082 46.12,19.285 58.335,19.285 58.843,19.793 58.843,23.857 59.09,24.104 P1.L3@59.09,25.34
NetQ1_1: Q1.1 R1.1 | length 7.1
  Top Layer w0.152: v2(13.589,34.798) 13.589,35.052 13.843,35.306 17.145,35.306 17.65,34.801 Q1.1@17.65,33.97
  Bottom Layer w0.152: R1.1@13.589,33.185 v2(13.589,34.798)
NetQ1_3: Q1.3 R3.2 | length 19.5
  Top Layer w0.152: Q1.3@20.45,33.02 21.463,33.02 v2(21.387,33.02)
  Bottom Layer w0.152: R3.2@19.558,22.06 18.834,21.336 17.399,21.336 17.018,21.717 17.018,32.512 17.526,33.02 v2(21.387,33.02)
NetQ2_1: Q2.1 R4.1 | length 8.4
  Top Layer w0.152: v2(14.986,34.798) 15.875,34.798 16.256,34.417 16.256,30.607 16.703,30.16 Q2.1@17.65,30.16
  Bottom Layer w0.152: R4.1@14.986,33.185 v2(14.986,34.798)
